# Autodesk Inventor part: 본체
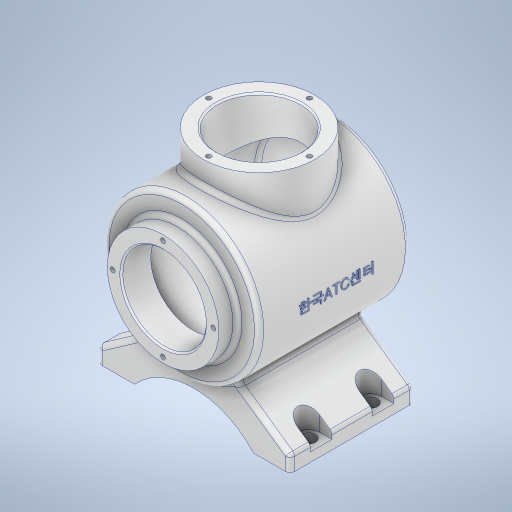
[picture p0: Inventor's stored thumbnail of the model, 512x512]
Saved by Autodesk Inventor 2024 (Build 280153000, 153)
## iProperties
Created: 2023-08
Part Number: 본체
Material: 알루미늄 6061
Document SubType Name: Modeling
Designer: Owner
Density: 2.7 g/cm^3
Appearance: 알루미늄 - 평지
Mass: 1296.75 g
Surface Area: 1060.33 cm^2
Volume: 480.277 cm^3
Author: Owner
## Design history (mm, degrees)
sketch "스케치1"
  geometry: L1 (0, 0)-(120, 0); L2 (0, 36)-(12, 36); L3 (12, 36)-(12, 50); L4 (12, 50)-(108.336, 50); L5 (103.887, 43)-(19, 43); L6 (19, 43)-(19, 27); L7 (19, 27)-(0, 27); L8 (0, 27)-(0, 36); A1 r 113 centre (7, 0) between (120, 0) and (108.336, 50); A2 r 106 centre (7, 0) between (113, 0) and (103.887, 43)
  constraints: 16 end point, 5 perpendicular, 4 point on circle, 3 horizontal, 2 centre point, 2 point on line, 1 concentric, 1 vertical alignment
  dimensions: "d20" = 120 distance of L1.start L1.end; "d21" = 113 radius of A1; "d22" = 7 radial gap between concentric circles of A1 A2; "d23" = 54 diameter of L7 L1; "d24" = 72 diameter of L2 L1; "d25" = 86 diameter of L5 L1; "d26" = 100 diameter of L4 L1; "d27" = 19 distance of L6.end L7.end; "d28" = 108 distance from line of L1.end L3
revolve "회전1" sketch "스케치1" stored, may be unused: angle "d29" = 90 deg
fillet "모깎기1" dims "d30" = 3
node "작업 평면1"
sketch "스케치2"
  geometry: L1 (0, 36)-(0, -36) reference; C1 r 36 at (-62, 0); 2 further points
  constraints: 1 centre point, 1 horizontal alignment, 1 midpoint
  dimensions: "d32" = 72 diameter of C1; "d33" = 62 distance from line of L1 C1.centre
extrude "돌출1" join sketch "스케치2" stored distance "d34" = 10; taper "d35" = 0 deg
sketch "스케치3"
  geometry: C1 r 36 at (0, 0) reference; 2 further points
  constraints: 1 coincident
hole "구멍1" sketch "스케치3" at (0, 0) diameter "d36" = 54; stored, may be unused: countersink angle "d40" = 90 deg, drill point angle "d42" = 0 deg; dims "d37" = 6, "d38" = 8, "d39" = 4.4, "d41" = 67
node "작업 평면2"
sketch "스케치4"
  geometry: L1 (-26.694, -42.278)-(-62, -67); L2 (-62, -67)-(-62, -77); L3 (-62, -77)-(-38.5, -77); L4 (38.5, -77)-(62, -77); L5 (62, -77)-(62, -67); L6 (62, -67)-(26.694, -42.278); A1 r 50 centre (0, 0) between (-26.694, -42.278) and (26.694, -42.278) reference; A2 r 52.096 centre (0, -112.096) between (38.5, -77) and (-38.5, -77); 2 further points
  constraints: 12 end point, 5 point on circle, 3 equal length, 2 perpendicular, 1 centre point, 1 horizontal, 1 horizontal alignment, 1 vertical
  dimensions: "d44" = 55 deg angle of L6 L5; "d45" = 55 deg angle of L2 L1; "d46" = 124 distance between parallel lines of L5 L2; "d47" = 10 distance of L4.end L5.end; "d48" = 77 distance from line of L3 point (0, 0); "d49" = 77 distance of L4.start L3.end; "d50" = 17 distance from line of point (0, -60) L4
extrude "돌출2" join sketch "스케치4" distance "d51" = 80; taper "d52" = 0 deg
node "작업 평면3"
sketch "스케치5"
  geometry: L1 (60, 15.5)-(60, 39.438); L2 (67, 15.5)-(67, 23.5); L3 (53, 23.5)-(53, 15.5); L4 (0, 23.5)-(80, 23.5) reference; L5 (80, 23.5)-(80, 0) reference; A1 r 7 centre (60, 15.5) between (53, 15.5) and (67, 15.5); 2 further points
  constraints: 8 end point, 2 point on circle, 2 point on line, 2 tangent, 2 vertical, 1 centre point, 1 midpoint, 1 parallel
  dimensions: "d54" = 14 distance between parallel lines of L3 L2; "d55" = 20 distance between parallel lines of L1 L5; "d56" = 8 distance from line of L4 L1.start
extrude "돌출3" cut sketch "스케치5" distance "d57" = 26.25; taper "d58" = 0 deg
sketch "스케치6"
  geometry: C1 r 4.5 at (60, -15.5); A1 r 7 centre (60, -15.5) between (67, -15.5) and (53, -15.5) reference; 1 further point
  constraints: 1 centre point, 1 concentric
  dimensions: "d59" = 9 diameter of C1
extrude "돌출4" cut sketch "스케치6" extent not by distance; stored distance "d60" = 0; taper "d61" = 0 deg
fillet "모깎기2" dims "d65" = 3
fillet "모깎기3" dims "d66" = 3
fillet "모깎기4" dims "d67" = 3
fillet "모깎기5" dims "d68" = 3
chamfer "모따기1" distance "d69" = 1; stored, may be unused: second distance "d70" = 2, angle "d71" = 45 deg
sketch "스케치7" dims "d72" = 65
  geometry: 3 further points
  constraints: 2 vertical alignment, 1 coincident, 2 other
hole "구멍2" sketch "스케치7" at (0, 32.5) diameter "d73" = 3.242; stored, may be unused: countersink angle "d77" = 90 deg, drill point angle "d79" = 118 deg; dims "d74" = 8, "d75" = 4, "d76" = 2, "d78" = 10
sketch "스케치8" dims "d83" = 65
  geometry: C1 r 36 at (0, 0) reference; 3 further points
  constraints: 2 vertical alignment, 1 coincident, 2 other
hole "구멍3" sketch "스케치8" at (0, 32.5) diameter "d84" = 3.242; stored, may be unused: countersink angle "d88" = 90 deg, drill point angle "d90" = 118 deg; dims "d85" = 8, "d86" = 4, "d87" = 2, "d89" = 10
node "작업 평면4"
sketch "스케치9"
  geometry: 1 further point
sketch "스케치10"
  geometry: L1 (-60.168, -36)-(-60.168, 36) reference; 2 further points
  constraints: 1 horizontal alignment, 1 other
  dimensions: "d94" = 62 distance from line of point (1.832, 0) L1
feature "엠보싱1" sketch "스케치10" dims "d95" = 0.5, "d96" = 0
feature "ɉ耀ɋ耀ɍ耀ɏ耀ɑ耀ɓ耀ɕ耀ɗ耀" dims "d20" = 120, "d21" = 113, "d22" = 7, "d23" = 54, "d24" = 72, "d25" = 86, "d26" = 100, "d27" = 19, "d28" = 108, "d29" = 90 deg, "d30" = 3, "d31" = 65, "d32" = 72, "d33" = 62, "d34" = 10, "d35" = 0, "d36" = 54, "d37" = 6, "d38" = 8, "d39" = 4.4, "d40" = 90 deg, "d41" = 67, "d42" = 0, "d43" = -20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
node "솔리드1"
pattern_linear "직사각형 패턴1" dims "d64" = 40
mirror "미러1"
pattern_circular "원형 패턴1" dims angle "d81" = 360 deg
pattern_circular "원형 패턴2" dims angle "d92" = 360 deg
feature "A9D066F2-1C7D-4E18-AEED-F7BC21143FA4" dims "d36" = 54, "d37" = 6, "d38" = 8, "d39" = 4.4, "d40" = 90 deg, "d41" = 67, "d42" = 0
